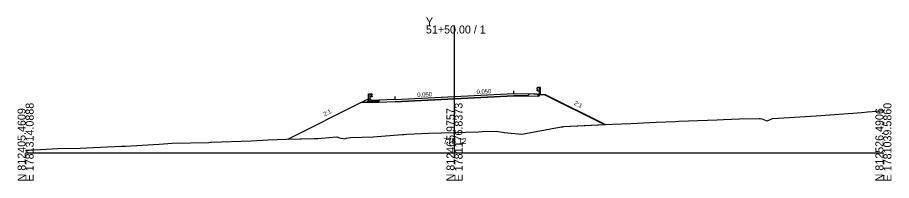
# Model space of a CAD drawing. Extents: x -12583 to 5303, y -44 to 25667.
# Drawn here: x 3997.2 to 4302.8, y 1990.3 to 2047.3 of the extents above; entities that cross this region are included whole.
import ezdxf

# ---------------------------------------------------------------- set-up
doc = ezdxf.new("R2010")
doc.units = 0
for name, color, linetype in [('Exist Cross Section Cell', 7, 'Continuous'), ('Exist XS Center Line Elevation Label', 7, 'Continuous'), ('Exist XS Ground Line', 7, 'Continuous'), ('Prop XS Dump Level', 7, 'Continuous'), ('Prop XS Earthwork Shape', 7, 'Continuous'), ('Prop XS EOT Tick Mark', 7, 'Continuous'), ('Prop XS Finish Grade', 7, 'Continuous'), ('Prop XS Finish Grade CurbGutter', 7, 'Continuous'), ('Prop XS Finish Grade Earthwork', 7, 'Continuous'), ('Prop XS Finish Grade Paved Shoulder', 7, 'Continuous'), ('Prop XS Finish Grade Pavement', 7, 'Continuous'), ('Prop XS Guardrail', 7, 'Continuous'), ('Prop XS Pvmt Edge Slope', 7, 'Continuous'), ('Prop XS SE Text', 7, 'Continuous'), ('Prop XS Side Slope Text', 7, 'Continuous'), ('Prop XS Subgrade CurbGutter', 7, 'Continuous'), ('Prop XS Subgrade Earthwork', 7, 'Continuous')]:
    doc.layers.add(name, color=color, linetype=linetype)

msp = doc.modelspace()

# ---------------------------------------------------------------- linework, layer by layer
at = {"layer": 'Exist Cross Section Cell'}
for p, q in [((4150, 2000), (4150, 2044.51)), ((4000, 2000), (4150, 2000)), ((4150, 2000), (4300, 2000))]:
    msp.add_line(p, q, dxfattribs=at)
at = {"layer": 'Exist XS Ground Line'}
for p, q in [((4294.49, 2014.32), (4296.05, 2014.48)), ((4296.05, 2014.48), (4300, 2014.84)), ((4228.43, 2011.01), (4238.51, 2011.43)), ((4238.51, 2011.43), (4241.83, 2011.58)), ((4241.83, 2011.58), (4244.11, 2011.65)), ((4244.11, 2011.65), (4249.68, 2011.88)), ((4249.68, 2011.88), (4256.52, 2011.99)), ((4256.52, 2011.99), (4256.94, 2012)), ((4256.94, 2012), (4257.46, 2011.82)), ((4257.46, 2011.82), (4259.18, 2011.13)), ((4259.18, 2011.13), (4259.94, 2011.43)), ((4259.94, 2011.43), (4261.17, 2012.03)), ((4261.17, 2012.03), (4263.35, 2012.13)), ((4263.35, 2012.13), (4274.55, 2012.75)), ((4274.55, 2012.75), (4276.48, 2012.87)), ((4276.48, 2012.87), (4292.45, 2014.13)), ((4292.45, 2014.13), (4294.49, 2014.32)), ((4173.53, 2006.5), (4186.68, 2009)), ((4186.68, 2009), (4187.26, 2009.1)), ((4187.26, 2009.1), (4187.9, 2009.13)), ((4187.9, 2009.13), (4188.29, 2009.14)), ((4188.29, 2009.14), (4205.29, 2010.01)), ((4205.29, 2010.01), (4211.64, 2010.3)), ((4211.64, 2010.3), (4220.57, 2010.68)), ((4220.57, 2010.68), (4227.25, 2010.98)), ((4227.25, 2010.98), (4228.43, 2011.01)), ((4103.45, 2005.07), (4108.83, 2005.59)), ((4108.83, 2005.59), (4109.82, 2005.28)), ((4109.82, 2005.28), (4111.62, 2004.9)), ((4112.28, 2005.12), (4113.68, 2005.38)), ((4113.68, 2005.38), (4121.59, 2005.62)), ((4121.59, 2005.62), (4131.67, 2006.42)), ((4131.67, 2006.42), (4132.29, 2006.45)), ((4132.29, 2006.45), (4133.34, 2006.52)), ((4133.34, 2006.52), (4140.86, 2006.86)), ((4140.86, 2006.86), (4150, 2007.12)), ((4150, 2007.12), (4153.9, 2007.23)), ((4153.9, 2007.23), (4158.33, 2007.36)), ((4158.33, 2007.36), (4159.67, 2007.42)), ((4159.67, 2007.42), (4164.65, 2007.54)), ((4164.65, 2007.54), (4167.38, 2007.14)), ((4167.38, 2007.14), (4173.53, 2006.5)), ((4021.3, 2001.68), (4033.48, 2002.31)), ((4033.48, 2002.31), (4034.95, 2002.37)), ((4034.95, 2002.37), (4046.68, 2003.03)), ((4046.68, 2003.03), (4051.26, 2003.31)), ((4051.26, 2003.31), (4064.06, 2003.65)), ((4064.06, 2003.65), (4064.67, 2003.67)), ((4064.67, 2003.67), (4065, 2003.69)), ((4065, 2003.69), (4078.85, 2004.24)), ((4078.85, 2004.24), (4084.8, 2004.5)), ((4084.8, 2004.5), (4091.1, 2004.81)), ((4091.1, 2004.81), (4100.97, 2004.99)), ((4100.97, 2004.99), (4102.26, 2005)), ((4102.26, 2005), (4103.45, 2005.07)), ((4111.62, 2004.9), (4112.28, 2005.12)), ((4000, 2000.79), (4000.65, 2000.81)), ((4000.65, 2000.81), (4001.98, 2000.99)), ((4001.98, 2000.99), (4005.21, 2001.15)), ((4005.21, 2001.15), (4011.29, 2001.52)), ((4011.29, 2001.52), (4019.09, 2001.56)), ((4019.09, 2001.56), (4021.3, 2001.68))]:
    msp.add_line(p, q, dxfattribs=at)
at = {"layer": 'Prop XS Dump Level'}
for p, q in [((4150, 2019.67), (4170.75, 2020.71)), ((4129.25, 2018.64), (4150, 2019.67))]:
    msp.add_line(p, q, dxfattribs=at)
at = {"layer": 'Prop XS Earthwork Shape'}
msp.add_lwpolyline([(4123.58, 2017.56), (4119.19, 2017.56), (4117.32, 2017.56), (4091.85, 2004.82), (4100.97, 2004.99), (4102.26, 2005), (4103.45, 2005.07), (4108.83, 2005.59), (4109.82, 2005.28), (4111.62, 2004.9), (4112.28, 2005.12), (4113.68, 2005.38), (4121.59, 2005.62), (4131.67, 2006.42), (4132.29, 2006.45), (4133.34, 2006.52), (4140.86, 2006.86), (4150, 2007.12), (4153.9, 2007.23), (4158.33, 2007.36), (4159.67, 2007.42), (4164.65, 2007.54), (4167.38, 2007.14), (4173.53, 2006.5), (4186.68, 2009), (4187.26, 2009.1), (4187.9, 2009.13), (4188.29, 2009.14), (4202.39, 2009.86), (4181.75, 2020.18), (4176.24, 2020.57), (4175.55, 2019.87), (4170.77, 2019.92), (4150.04, 2018.88), (4129.29, 2017.84)], close=True, dxfattribs=at)
at = {"layer": 'Prop XS EOT Tick Mark'}
for p, q in [((4170.75, 2020.71), (4170.75, 2021.71)), ((4129.25, 2018.64), (4129.25, 2019.64))]:
    msp.add_line(p, q, dxfattribs=at)
at = {"layer": 'Prop XS Finish Grade'}
for p, q in [((4178.75, 2020.63), (4180.24, 2020.53)), ((4117.32, 2017.56), (4119.98, 2018.89)), ((4120.56, 2018.6), (4119.98, 2018.89))]:
    msp.add_line(p, q, dxfattribs=at)
at = {"layer": 'Prop XS Finish Grade CurbGutter'}
for p, q in [((4121.25, 2018.26), (4120.56, 2018.6)), ((4123.58, 2018.35), (4121.25, 2018.26))]:
    msp.add_line(p, q, dxfattribs=at)
at = {"layer": 'Prop XS Finish Grade Earthwork'}
for p, q in [((4117.32, 2017.56), (4091.85, 2004.82)), ((4180.24, 2020.53), (4181.75, 2020.42)), ((4181.75, 2020.42), (4202.83, 2009.88))]:
    msp.add_line(p, q, dxfattribs=at)
at = {"layer": 'Prop XS Finish Grade Paved Shoulder'}
for p, q in [((4170.75, 2020.71), (4178.75, 2020.63)), ((4129.25, 2018.64), (4123.58, 2018.35))]:
    msp.add_line(p, q, dxfattribs=at)
at = {"layer": 'Prop XS Finish Grade Pavement'}
for p, q in [((4150, 2019.67), (4170.75, 2020.71)), ((4129.25, 2018.64), (4150, 2019.67))]:
    msp.add_line(p, q, dxfattribs=at)
at = {"layer": 'Prop XS Guardrail'}
for p, q in [((4119.93, 2020.65), (4120.43, 2020.65)), ((4119.93, 2018.15), (4119.93, 2020.65)), ((4120.43, 2020.65), (4120.93, 2020.65)), ((4120.43, 2020.65), (4120.43, 2018.15)), ((4120.93, 2020.65), (4121.22, 2020.45)), ((4178.78, 2022.6), (4178.75, 2022.54)), ((4178.75, 2022.54), (4178.78, 2022.48)), ((4178.78, 2021.98), (4178.75, 2021.92)), ((4178.75, 2021.92), (4178.78, 2021.86)), ((4179.07, 2022.8), (4178.78, 2022.6)), ((4178.78, 2022.48), (4179.07, 2022.28)), ((4179.07, 2022.18), (4178.78, 2021.98)), ((4178.78, 2021.86), (4179.07, 2021.66)), ((4179.57, 2022.8), (4179.07, 2022.8)), ((4179.07, 2022.28), (4179.07, 2022.18)), ((4179.07, 2021.66), (4179.57, 2021.66)), ((4180.07, 2022.8), (4179.57, 2022.8)), ((4179.57, 2022.8), (4179.57, 2020.3)), ((4180.07, 2020.3), (4180.07, 2022.8)), ((4120.93, 2019.52), (4120.43, 2019.52)), ((4121.22, 2020.33), (4120.93, 2020.13)), ((4120.93, 2020.13), (4120.93, 2020.04)), ((4120.93, 2020.04), (4121.22, 2019.84)), ((4121.22, 2019.72), (4120.93, 2019.52)), ((4121.22, 2020.45), (4121.25, 2020.39)), ((4121.25, 2020.39), (4121.22, 2020.33)), ((4121.22, 2019.84), (4121.25, 2019.78)), ((4121.25, 2019.78), (4121.22, 2019.72))]:
    msp.add_line(p, q, dxfattribs=at)
at = {"layer": 'Prop XS Pvmt Edge Slope'}
for p, q in [((4178.75, 2020.63), (4179.55, 2019.83)), ((4119.56, 2017.93), (4119.19, 2017.56)), ((4120.56, 2017.93), (4119.56, 2017.93))]:
    msp.add_line(p, q, dxfattribs=at)
at = {"layer": 'Prop XS Subgrade CurbGutter'}
for p, q in [((4120.56, 2017.93), (4120.56, 2018.6)), ((4123.58, 2017.93), (4120.56, 2017.93)), ((4123.58, 2018.35), (4123.58, 2017.93))]:
    msp.add_line(p, q, dxfattribs=at)
at = {"layer": 'Prop XS Subgrade Earthwork'}
for p, q in [((4119.19, 2017.56), (4117.32, 2017.56)), ((4123.58, 2017.56), (4119.19, 2017.56)), ((4129.29, 2017.84), (4123.58, 2017.56)), ((4129.29, 2017.84), (4150.04, 2018.88)), ((4150.04, 2018.88), (4170.77, 2019.92)), ((4170.77, 2019.92), (4179.55, 2019.83)), ((4179.55, 2019.83), (4180.24, 2020.53))]:
    msp.add_line(p, q, dxfattribs=at)

# ---------------------------------------------------------------- texts
at = {"layer": 'Exist Cross Section Cell'}
for s, p in [('Y', (4140, 2044.51)), ('51+50.00 / 1', (4140, 2041.71))]:
    msp.add_text(s, height=2.8, dxfattribs=at).set_placement(p)
for s, p in [('N 812405.4609', (4000, 1990)), ('E 1781314.0888', (4002.8, 1990)), ('N 812465.9757', (4150, 1990)), ('E 1781176.8373', (4152.8, 1990)), ('N 812526.4906', (4300, 1990)), ('E 1781039.5860', (4302.8, 1990))]:
    msp.add_text(s, height=2.8, rotation=90, dxfattribs=at).set_placement(p)
at = {"layer": 'Exist XS Center Line Elevation Label'}
msp.add_text('775.12', height=2, dxfattribs=at).set_placement((4146.03, 2003.12))
at = {"layer": 'Prop XS Dump Level'}
msp.add_text('Case2', height=0.04, dxfattribs=at).set_placement((4178.75, 2020.35))
at = {"layer": 'Prop XS SE Text'}
for p in [(4137, 2019.52), (4157.75, 2020.56)]:
    msp.add_text('0.050', height=1.5, rotation=2.8624, dxfattribs=at).set_placement(p)
at = {"layer": 'Prop XS Side Slope Text'}
for rotation, p in [(333.4349, (4191.66, 2016.9)), (26.5651, (4104.53, 2012.69))]:
    msp.add_text('2:1', height=1.5, rotation=rotation, dxfattribs=at).set_placement(p)

doc.saveas('drawing.dxf')
